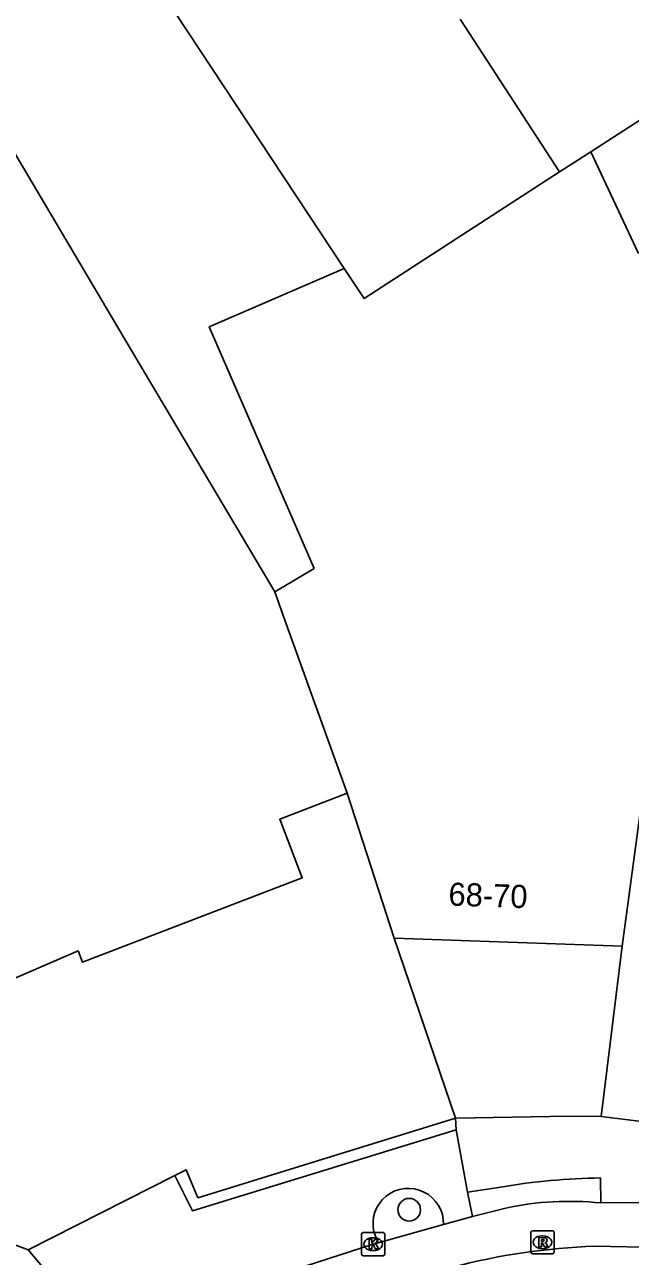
# Model space of a CAD drawing. Extents: x 160861 to 161308, y 384024 to 384878.
# Drawn here: x 161083.4 to 161109.6, y 384422.3 to 384475.6 of the extents above; entities that cross this region are included whole.
import ezdxf

# ---------------------------------------------------------------- set-up
doc = ezdxf.new("R2010")
doc.units = 0
for name, color, linetype in [('IMGEO_Boom', 7, 'Continuous'), ('IMGEO_Kolk', 7, 'Continuous'), ('IMGEO_Pand', 7, 'Continuous'), ('IMGEO_Pand_nummerreeks', 7, 'Continuous'), ('IMGEO_Parkeervlak_open', 7, 'Continuous'), ('IMGEO_Rijbaan_lokaal_open', 7, 'Continuous'), ('IMGEO_Rioolput', 7, 'Continuous'), ('IMGEO_Voetpad_open', 7, 'Continuous')]:
    doc.layers.add(name, color=color, linetype=linetype)

msp = doc.modelspace()

# ---------------------------------------------------------------- linework, layer by layer
at = {"layer": 'IMGEO_Boom'}
msp.add_circle((161100.02, 384424.28), 0.489, dxfattribs=at)
at = {"layer": 'IMGEO_Kolk'}
for p, q in [((161097.958, 384422.362), (161097.958, 384423.214)), ((161098.033, 384423.288), (161098.885, 384423.288)), ((161098.959, 384423.214), (161098.959, 384422.362)), ((161098.446, 384423.068), (161098.471, 384423.068)), ((161098.885, 384422.288), (161098.033, 384422.288)), ((161098.469, 384422.508), (161098.444, 384422.508))]:
    msp.add_line(p, q, dxfattribs=at)
for points in [[(161097.958, 384422.362), (161097.958, 384423.214)], [(161098.033, 384423.288), (161098.885, 384423.288)], [(161098.959, 384423.214), (161098.959, 384422.362)], [(161098.279, 384422.988), (161098.402, 384422.988), (161098.402, 384422.837), (161098.532, 384422.988), (161098.696, 384422.988), (161098.55, 384422.837), (161098.703, 384422.588), (161098.551, 384422.588), (161098.466, 384422.752), (161098.402, 384422.685), (161098.402, 384422.588), (161098.279, 384422.588), (161098.279, 384422.988)], [(161098.885, 384422.288), (161098.033, 384422.288)]]:
    msp.add_lwpolyline(points, dxfattribs=at)
for centre, start, end in [((161098.035, 384423.212), 91.552, 178.448), ((161098.035, 384423.212), 91.552, 178.448), ((161098.883, 384423.212), 1.552, 88.448), ((161098.883, 384423.212), 1.552, 88.448), ((161098.035, 384422.364), 181.552, 268.448), ((161098.035, 384422.364), 181.552, 268.448), ((161098.883, 384422.364), 271.552, 358.448), ((161098.883, 384422.364), 271.552, 358.448)]:
    msp.add_arc(centre, 0.0765, start, end, dxfattribs=at)
for centre, major_axis, ratio, start_param, end_param in [((161098.445, 384422.788), (-0.387, 0.002), 0.722429, 4.712389, 7.853982), ((161098.47, 384422.788), (-0.39, 0.002), 0.717154, 1.570796, 4.712389)]:
    msp.add_ellipse(centre, major_axis=major_axis, ratio=ratio, start_param=start_param, end_param=end_param, dxfattribs=at)
at = {"layer": 'IMGEO_Pand'}
for points in [[(161127.791, 384482.982), (161107.881, 384470.092)], [(161088.869, 384477.676), (161097.209, 384465.039)], [(161106.522, 384469.213), (161102.22, 384475.828)], [(161094.201, 384451.035), (161087.735, 384461.947), (161080.492, 384474.172), (161079.386, 384473.255)], [(161107.881, 384470.092), (161106.522, 384469.213)], [(161109.942, 384465.677), (161107.881, 384470.092)], [(161106.522, 384469.213), (161098.067, 384463.739), (161097.209, 384465.039)], [(161097.209, 384465.039), (161091.365, 384462.502), (161095.906, 384452.045), (161094.201, 384451.035)], [(161094.201, 384451.035), (161094.568, 384450.014), (161097.341, 384442.312)], [(161097.341, 384442.312), (161094.42, 384441.188), (161095.394, 384438.657), (161085.88, 384434.994), (161085.69, 384435.488), (161077.552, 384431.965)], [(161097.341, 384442.312), (161099.363, 384436.033)], [(161109.228, 384435.688), (161110.053, 384441.789)], [(161102.025, 384428.239), (161099.363, 384436.033)], [(161099.363, 384436.033), (161109.228, 384435.688)], [(161109.228, 384435.688), (161108.316, 384428.314)], [(161077.552, 384431.965), (161077.145, 384431.612), (161081.445, 384423.321), (161083.529, 384422.548)], [(161089.882, 384425.764), (161090.367, 384426.009), (161090.875, 384424.797), (161102.025, 384428.239)], [(161108.316, 384428.314), (161114.167, 384427.59)], [(161089.882, 384425.764), (161083.529, 384422.548)]]:
    msp.add_lwpolyline(points, dxfattribs=at)
at = {"layer": 'IMGEO_Parkeervlak_open'}
msp.add_lwpolyline([(161101.502, 384423.64), (161098.674, 384422.848)], dxfattribs=at)
at = {"layer": 'IMGEO_Rijbaan_lokaal_open'}
msp.add_lwpolyline([(161110.83, 384422.646), (161108.046, 384422.701)], dxfattribs=at)
msp.add_arc((161109.008, 384394.985), 27.732, 91.9872, 104.9017, dxfattribs=at)
at = {"layer": 'IMGEO_Rioolput'}
for p, q in [((161105.286, 384422.445), (161105.286, 384423.297)), ((161105.361, 384423.371), (161106.213, 384423.371)), ((161105.774, 384423.151), (161105.799, 384423.151)), ((161106.287, 384423.297), (161106.287, 384422.445)), ((161105.797, 384422.591), (161105.772, 384422.591)), ((161106.213, 384422.371), (161105.361, 384422.371))]:
    msp.add_line(p, q, dxfattribs=at)
for points in [[(161105.286, 384422.445), (161105.286, 384423.297)], [(161105.361, 384423.371), (161106.213, 384423.371)], [(161106.287, 384423.297), (161106.287, 384422.445)], [(161105.875, 384423.069), (161105.623, 384423.071), (161105.623, 384422.671)], [(161105.623, 384422.671), (161105.747, 384422.671), (161105.747, 384422.833), (161105.758, 384422.833)], [(161105.801, 384422.99), (161105.747, 384422.99), (161105.747, 384422.909)], [(161105.747, 384422.909), (161105.799, 384422.909)], [(161105.805, 384422.804), (161105.876, 384422.671), (161106.016, 384422.671), (161105.951, 384422.797)], [(161106.213, 384422.371), (161105.361, 384422.371)]]:
    msp.add_lwpolyline(points, dxfattribs=at)
for centre, radius, start, end in [((161105.363, 384423.295), 0.0765, 91.552, 178.448), ((161105.363, 384423.295), 0.0765, 91.552, 178.448), ((161106.211, 384423.295), 0.0765, 1.552, 88.448), ((161106.211, 384423.295), 0.0765, 1.552, 88.448), ((161105.757, 384422.78), 0.0533, 26.0293, 88.6989), ((161105.783, 384423.098), 0.19, 274.7715, 282.9687), ((161105.807, 384422.894), 0.0964, 77.0061, 93.1865), ((161105.821, 384422.951), 0.0378, 276.6634, 79.6772), ((161105.874, 384422.959), 0.109, 350.3612, 89.416), ((161105.872, 384422.959), 0.112, 277.5842, 350.9817), ((161105.856, 384422.744), 0.108, 29.5134, 73.7905), ((161105.363, 384422.447), 0.0765, 181.552, 268.448), ((161105.363, 384422.447), 0.0765, 181.552, 268.448), ((161106.211, 384422.447), 0.0765, 271.552, 358.448), ((161106.211, 384422.447), 0.0765, 271.552, 358.448)]:
    msp.add_arc(centre, radius, start, end, dxfattribs=at)
for centre, major_axis, ratio, start_param, end_param in [((161105.773, 384422.871), (-0.387, 0.002), 0.722429, 4.712389, 7.853982), ((161105.798, 384422.871), (-0.39, 0.002), 0.717154, 1.570796, 4.712389)]:
    msp.add_ellipse(centre, major_axis=major_axis, ratio=ratio, start_param=start_param, end_param=end_param, dxfattribs=at)
at = {"layer": 'IMGEO_Voetpad_open'}
for points in [[(161108.316, 384428.314), (161106.917, 384428.332), (161102.025, 384428.239)], [(161102.025, 384428.239), (161102.043, 384427.734)], [(161102.043, 384427.734), (161090.636, 384424.238), (161089.882, 384425.764)], [(161102.539, 384425.039), (161102.043, 384427.734)], [(161102.539, 384425.039), (161103.986, 384425.26)], [(161108.301, 384425.657), (161108.306, 384424.573)], [(161102.76, 384423.992), (161102.539, 384425.039)], [(161104.201, 384424.352), (161102.76, 384423.992)], [(161108.306, 384424.573), (161113.205, 384424.617), (161116.057, 384424.417), (161130.131, 384423.013)], [(161101.502, 384423.64), (161102.76, 384423.992)], [(161098.674, 384422.848), (161098.494, 384423.32)], [(161091.056, 384420.394), (161098.459, 384422.788), (161098.674, 384422.848)], [(161083.529, 384422.548), (161087.978, 384417.265)]]:
    msp.add_lwpolyline(points, dxfattribs=at)
for centre, radius, start, end in [((161108.674, 384397.949), 27.71, 90.7722, 99.7411), ((161099.977, 384423.68), 1.526, 358.5045, 193.6404), ((161106.96, 384411.336), 13.306, 84.1948, 101.9684)]:
    msp.add_arc(centre, radius, start, end, dxfattribs=at)

# ---------------------------------------------------------------- texts
at = {"layer": 'IMGEO_Pand_nummerreeks'}
msp.add_text('68-70', height=1, rotation=357.9946, dxfattribs=at).set_placement((161101.703, 384437.452))

doc.saveas('drawing.dxf')
